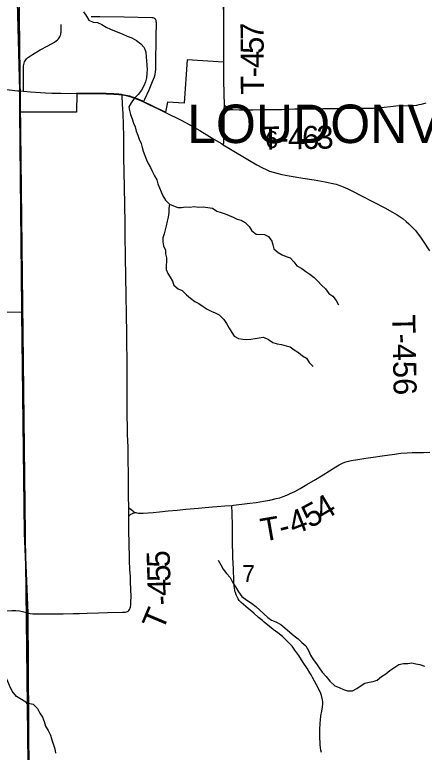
# Model space of a CAD drawing. Extents: x -7.5 to 53.5, y 0 to 22.
# Drawn here: x 4.57 to 5.577, y 15.27 to 17.086 of the extents above; entities that cross this region are included whole.
import ezdxf

# ---------------------------------------------------------------- set-up
doc = ezdxf.new("R2010")
doc.units = 0
for name, color, linetype in [('GM_X_City_Street', 7, 'Continuous'), ('GM_X_Corporation', 7, 'Continuous'), ('GM_X_Corporation_Text', 7, 'Continuous'), ('GM_X_Minor_River', 7, 'Continuous'), ('GM_X_Section_Text', 7, 'Continuous'), ('GM_X_State_Route', 7, 'Continuous'), ('GM_X_Township_Road', 7, 'Continuous'), ('GM_X_Township_Road_Text', 7, 'Continuous'), ('SH_Data', 7, 'Continuous')]:
    doc.layers.add(name, color=color, linetype=linetype)

msp = doc.modelspace()

# ---------------------------------------------------------------- linework, layer by layer
at = {"layer": 'GM_X_City_Street'}
for points in [[(4.7575, 17.0819), (4.7794, 17.0816), (4.8388, 17.0806), (4.9069, 17.0795), (4.9095, 17.0792), (4.9118, 17.0787), (4.9131, 17.0781), (4.9141, 17.0774), (4.9151, 17.0763), (4.9159, 17.0754)], [(4.887, 16.8716), (4.89, 16.8786), (4.9002, 16.9015), (4.9087, 16.9217), (4.9133, 16.9333), (4.9151, 16.9392), (4.9163, 16.9452), (4.917, 16.9514), (4.9173, 16.9638), (4.9179, 17.0327), (4.9183, 17.0665), (4.9181, 17.0689), (4.918, 17.07), (4.9177, 17.0712), (4.9174, 17.0723), (4.9171, 17.0733), (4.9165, 17.0745), (4.9159, 17.0754)], [(4.5916, 16.8979), (4.5916, 16.9055), (4.5916, 16.9147), (4.5915, 16.93), (4.5912, 16.9515), (4.5916, 16.9607), (4.5919, 16.9636), (4.5927, 16.9673), (4.5937, 16.9702), (4.5951, 16.9729), (4.5968, 16.9755), (4.5988, 16.9778), (4.601, 16.9799), (4.6059, 16.9837), (4.6138, 16.9886), (4.6325, 16.9994), (4.6513, 17.0099), (4.6674, 17.019), (4.6725, 17.0225), (4.6749, 17.0244), (4.6771, 17.0266), (4.679, 17.029), (4.6806, 17.0316), (4.6819, 17.0344), (4.6829, 17.0373), (4.6836, 17.0404), (4.6839, 17.0434), (4.6841, 17.0496), (4.6839, 17.0619)]]:
    msp.add_lwpolyline(points, dxfattribs=at)
at = {"layer": 'GM_X_Corporation'}
for points in [[(4.6087, 14.5302), (4.6021, 15.6139), (4.594, 15.8096), (4.5873, 16.3533), (4.5872, 16.3635), (4.5826, 16.8462), (4.5822, 16.8992), (4.577, 17.1178), (4.5749, 17.2575), (4.5771, 17.6201), (4.5718, 18.1276), (4.5696, 18.2604), (4.5565, 19.1354), (5.0411, 19.1401), (6.0424, 19.1527), (6.0433, 19.1527), (6.5522, 19.1561), (7.544, 19.1455), (8.414, 19.1709), (8.5159, 19.1718), (8.9, 19.1887), (8.9, 20.9), (2.1, 20.9), (2.1, 14.1)], [(8.9, 14.1), (8.9, 19.1887), (8.5159, 19.1718), (8.414, 19.1709), (7.544, 19.1455), (6.5522, 19.1561), (6.0433, 19.1527), (6.0424, 19.1527), (5.0411, 19.1401), (4.5565, 19.1354), (4.5696, 18.2604), (4.5718, 18.1276), (4.5771, 17.6201), (4.5749, 17.2575), (4.577, 17.1178), (4.5822, 16.8992), (4.5826, 16.8462), (4.5872, 16.3635), (4.5873, 16.3533), (4.594, 15.8096), (4.6021, 15.6139), (4.6087, 14.5302)], [(5.0833, 17.1238), (5.0837, 16.9694), (4.9938, 16.9748), (4.9864, 16.8684), (4.9457, 16.8713), (4.9407, 16.8459), (4.9209, 16.8557), (4.9011, 16.8652), (4.8868, 16.8721), (4.8846, 16.8733), (4.8731, 16.878), (4.8617, 16.8824), (4.8529, 16.8854), (4.8439, 16.8876), (4.8348, 16.8893), (4.8335, 16.8895), (4.8256, 16.8905), (4.8133, 16.8915), (4.7947, 16.8921), (4.7224, 16.8928), (4.722, 16.8462), (4.5826, 16.8462), (4.5873, 16.3533), (3.9378, 16.3588)]]:
    msp.add_lwpolyline(points, dxfattribs=at)
at = {"layer": 'GM_X_Minor_River'}
for points in [[(4.7393, 17.0935), (4.746, 17.0825), (4.7524, 17.0729), (4.763, 17.0679), (4.7732, 17.0667), (4.7838, 17.062), (4.7947, 17.0559), (4.8056, 17.0504), (4.8155, 17.0469), (4.8257, 17.0423), (4.8355, 17.038), (4.8464, 17.0338), (4.8581, 17.0291), (4.8698, 17.0229), (4.8804, 17.0149), (4.8879, 17.0053), (4.8927, 16.9943), (4.893, 16.9822), (4.8944, 16.9723), (4.8947, 16.9617), (4.8954, 16.9514), (4.8949, 16.9412), (4.8941, 16.931), (4.8917, 16.9211), (4.8871, 16.9113), (4.8817, 16.9003), (4.8733, 16.8894), (4.8637, 16.8797), (4.8564, 16.8695), (4.8507, 16.8597), (4.8525, 16.8502), (4.8547, 16.8403), (4.8588, 16.8296), (4.8617, 16.8194), (4.8658, 16.8099), (4.8688, 16.7996), (4.8725, 16.7897), (4.8762, 16.7802), (4.8806, 16.7691), (4.8832, 16.7596), (4.8862, 16.7501), (4.8902, 16.7399), (4.8943, 16.7292), (4.8984, 16.7197), (4.9036, 16.7102), (4.9085, 16.6991), (4.9133, 16.6892), (4.9193, 16.6797), (4.9219, 16.6698), (4.926, 16.6599), (4.9304, 16.65), (4.9341, 16.6401), (4.9405, 16.6298), (4.9503, 16.6199), (4.9601, 16.616), (4.9707, 16.6113), (4.9802, 16.6116), (4.9896, 16.6131), (5.0006, 16.6122), (5.0109, 16.6144), (5.0218, 16.612), (5.0336, 16.6134), (5.045, 16.6118), (5.0567, 16.6098), (5.0673, 16.6029), (5.0775, 16.5994), (5.0873, 16.5963), (5.0971, 16.5916), (5.1069, 16.5877), (5.1171, 16.5831), (5.127, 16.58), (5.1368, 16.5746), (5.1465, 16.5646)], [(4.9503, 16.6199), (4.9487, 16.6093), (4.9493, 16.599), (4.9477, 16.5877), (4.9446, 16.5778), (4.9423, 16.5665), (4.9375, 16.5468), (4.9344, 16.5366), (4.934, 16.5267), (4.9362, 16.5172), (4.9406, 16.5069), (4.9405, 16.4975), (4.9431, 16.488), (4.943, 16.4785), (4.9422, 16.4686), (4.9425, 16.4591), (4.9466, 16.4493), (4.9522, 16.4397), (4.9582, 16.4302), (4.9615, 16.4203), (4.9717, 16.4111), (4.9819, 16.4072), (4.9928, 16.3969), (5.0026, 16.3885), (5.0127, 16.3804), (5.0225, 16.3754), (5.0331, 16.3681), (5.0429, 16.3615), (5.0531, 16.3561), (5.0629, 16.3526), (5.0731, 16.3472), (5.084, 16.3358), (5.0907, 16.3258), (5.0971, 16.3144), (5.1038, 16.3041), (5.1098, 16.2946), (5.12, 16.2892), (5.131, 16.2872), (5.1408, 16.2867), (5.1511, 16.2874), (5.1617, 16.2892), (5.1712, 16.291), (5.1818, 16.2924), (5.1939, 16.2862), (5.2048, 16.2789), (5.2154, 16.2758), (5.2264, 16.2742), (5.2373, 16.271), (5.2472, 16.2683), (5.2574, 16.261), (5.2679, 16.2545), (5.2781, 16.2464), (5.2879, 16.2403), (5.2942, 16.2303), (5.3033, 16.2208), (5.304, 16.2204)], [(5.1465, 16.5646), (5.1533, 16.5543), (5.1642, 16.5455), (5.1843, 16.5453), (5.1941, 16.5399), (5.202, 16.5289), (5.2049, 16.5194), (5.2075, 16.5095), (5.2176, 16.501), (5.2278, 16.4949), (5.238, 16.491), (5.2479, 16.4879), (5.2565, 16.4779), (5.2636, 16.468), (5.2761, 16.4611), (5.2859, 16.4538), (5.2957, 16.4472), (5.3062, 16.4388), (5.316, 16.4296), (5.325, 16.42), (5.3348, 16.4109), (5.343, 16.3998), (5.3528, 16.3929), (5.3607, 16.3826), (5.3667, 16.3723), (5.3663, 16.3719)], [(5.07, 15.7435), (5.0773, 15.7318), (5.0827, 15.7213), (5.0912, 15.7103), (5.0996, 15.7005), (5.1058, 15.6888), (5.1127, 15.6775), (5.12, 15.665), (5.1288, 15.6541), (5.1406, 15.6447), (5.1525, 15.6372), (5.1628, 15.629), (5.1731, 15.62), (5.1922, 15.6019), (5.2017, 15.5955), (5.212, 15.5915), (5.2242, 15.5847), (5.2341, 15.5768), (5.2471, 15.5663), (5.2574, 15.5573), (5.2669, 15.5494), (5.2765, 15.5408), (5.2864, 15.5321), (5.2926, 15.5208), (5.2976, 15.5091), (5.3038, 15.4989), (5.3126, 15.4883), (5.3187, 15.4782), (5.326, 15.4672), (5.3363, 15.4571), (5.3448, 15.4457), (5.3578, 15.4341), (5.368, 15.43), (5.3787, 15.4244), (5.3882, 15.4211), (5.4007, 15.4219), (5.4113, 15.427), (5.4218, 15.435), (5.4316, 15.4404), (5.4418, 15.4431), (5.4517, 15.4447), (5.4619, 15.4475), (5.4724, 15.4567), (5.4825, 15.4636), (5.4931, 15.4713), (5.5051, 15.4797), (5.5153, 15.4862), (5.5266, 15.489), (5.5373, 15.4887), (5.5471, 15.4903), (5.557, 15.4881), (5.5665, 15.4863), (5.5782, 15.4822)], [(4.5998, 15.3899), (4.5998, 15.3918), (4.5861, 15.4), (4.5742, 15.4075), (4.5631, 15.4203), (4.5573, 15.4343), (4.5511, 15.4486), (4.5457, 15.4603), (4.5388, 15.4717), (4.5303, 15.483), (4.5185, 15.4927), (4.5063, 15.5006), (4.4956, 15.5054), (4.485, 15.5095), (4.4728, 15.5151), (4.4651, 15.5256), (4.4593, 15.5377), (4.455, 15.5509), (4.4511, 15.563)], [(4.5998, 15.3918), (4.6155, 15.3884), (4.6255, 15.3779), (4.6316, 15.3669), (4.6378, 15.3567), (4.6421, 15.3458), (4.6456, 15.3348), (4.6517, 15.3235), (4.6575, 15.3125), (4.6607, 15.3008), (4.6642, 15.2906), (4.6681, 15.2785), (4.6697, 15.2682)]]:
    msp.add_lwpolyline(points, dxfattribs=at)
at = {"layer": 'GM_X_State_Route'}
msp.add_line((4.5824, 16.8987), (4.5916, 16.8979), dxfattribs=at)
for points in [[(4.5083, 16.9057), (4.5157, 16.9051), (4.5373, 16.9029), (4.556, 16.9011), (4.5777, 16.8991), (4.5824, 16.8987)], [(4.5916, 16.8979), (4.6083, 16.8965), (4.6456, 16.8939), (4.6612, 16.8933), (4.6832, 16.8927), (4.7226, 16.8923), (4.7949, 16.8916), (4.8135, 16.8909), (4.8258, 16.8899), (4.8337, 16.8889)], [(4.8337, 16.8889), (4.835, 16.8888), (4.8441, 16.8871), (4.8531, 16.8848), (4.8619, 16.8818), (4.8734, 16.8774), (4.8849, 16.8728), (4.887, 16.8716)], [(4.887, 16.8716), (4.9013, 16.8647), (4.9211, 16.8552), (4.9409, 16.8453)], [(4.9409, 16.8453), (4.979, 16.8267), (5.0009, 16.8149), (5.025, 16.8009), (5.0596, 16.7801), (5.0783, 16.7688), (5.0829, 16.766)], [(5.0829, 16.766), (5.0967, 16.7578), (5.1474, 16.7274), (5.1656, 16.7166), (5.1797, 16.709), (5.1882, 16.705), (5.1964, 16.7014), (5.2054, 16.6982), (5.2145, 16.6959), (5.2268, 16.693), (5.2451, 16.6899), (5.2788, 16.6841), (5.3062, 16.6797), (5.3337, 16.675), (5.3488, 16.6718), (5.3608, 16.6687), (5.3696, 16.6659), (5.3782, 16.6625), (5.3895, 16.6575), (5.4023, 16.6512), (5.4228, 16.6406), (5.4806, 16.6105), (5.4997, 16.6001), (5.5104, 16.5938), (5.5181, 16.5887), (5.5256, 16.5833), (5.5328, 16.5774), (5.5397, 16.5712), (5.5463, 16.5647), (5.5548, 16.5557), (5.5606, 16.5486), (5.5698, 16.5361), (5.575, 16.5284), (5.59, 16.5048)]]:
    msp.add_lwpolyline(points, dxfattribs=at)
at = {"layer": 'GM_X_Township_Road'}
for points in [[(5.0839, 16.9689), (5.0839, 16.9888), (5.084, 16.9961), (5.084, 17.0058), (5.0841, 17.0141), (5.0842, 17.0233), (5.0843, 17.0368), (5.0844, 17.0475), (5.0844, 17.0541), (5.0844, 17.0598), (5.0843, 17.066), (5.0841, 17.0767), (5.084, 17.0858), (5.0839, 17.0941), (5.0838, 17.1028), (5.0837, 17.1094), (5.0836, 17.113), (5.0835, 17.1188), (5.0835, 17.1232), (5.0834, 17.1243)], [(5.0856, 16.8635), (5.0856, 16.8644), (5.0856, 16.8734), (5.0855, 16.8827), (5.0851, 16.9004), (5.0847, 16.9164), (5.0842, 16.9347), (5.0841, 16.9407), (5.0841, 16.9502), (5.0839, 16.9689)], [(4.846, 16.2638), (4.8459, 16.2721), (4.8454, 16.3032), (4.8446, 16.3466), (4.8444, 16.3653), (4.8441, 16.3786), (4.8439, 16.3923), (4.8436, 16.409), (4.8433, 16.4274), (4.8428, 16.4584), (4.8425, 16.4739), (4.8422, 16.5048), (4.8419, 16.5295), (4.8417, 16.5512), (4.8413, 16.5792), (4.8408, 16.6113), (4.8404, 16.6289), (4.8401, 16.6506), (4.8395, 16.6755), (4.8393, 16.6848), (4.8388, 16.7096), (4.8385, 16.7251), (4.8386, 16.75), (4.8383, 16.7686), (4.838, 16.7873), (4.8372, 16.8152), (4.8362, 16.8431), (4.8352, 16.8649), (4.8339, 16.8864), (4.8337, 16.8889)], [(5.2713, 16.8543), (5.2912, 16.8546), (5.3232, 16.8548), (5.3293, 16.855), (5.3352, 16.8552), (5.3409, 16.8555), (5.3538, 16.8556), (5.3745, 16.8557), (5.389, 16.856), (5.4124, 16.8563), (5.4242, 16.8565), (5.4381, 16.8564), (5.4526, 16.8562), (5.4628, 16.857), (5.4722, 16.8579), (5.4785, 16.8585), (5.494, 16.8603), (5.5076, 16.8617), (5.5233, 16.8625), (5.5395, 16.862), (5.5462, 16.8624), (5.552, 16.8626), (5.5588, 16.8639), (5.5648, 16.865), (5.5705, 16.8662), (5.5824, 16.8695)], [(5.0854, 16.848), (5.0855, 16.8537), (5.0856, 16.8635)], [(5.0854, 16.848), (5.0898, 16.85), (5.0933, 16.8512), (5.0956, 16.8519), (5.0969, 16.8522), (5.0983, 16.8524), (5.0993, 16.8525)], [(5.0856, 16.8635), (5.0915, 16.8587), (5.095, 16.856), (5.0993, 16.8525)], [(5.0993, 16.8525), (5.1, 16.8526), (5.1062, 16.8527), (5.1217, 16.8523), (5.1372, 16.8522), (5.1558, 16.8522), (5.1788, 16.8525), (5.1932, 16.8527), (5.2272, 16.8532), (5.2583, 16.8541), (5.2713, 16.8543)], [(5.0829, 16.766), (5.0833, 16.768), (5.084, 16.7707), (5.0844, 16.7739), (5.0847, 16.7787), (5.0847, 16.7818), (5.0847, 16.788), (5.0848, 16.8035), (5.0848, 16.8082), (5.0848, 16.8136), (5.0848, 16.8183), (5.085, 16.8259), (5.0853, 16.8377), (5.0854, 16.8436), (5.0854, 16.848)], [(4.8495, 15.9561), (4.8491, 15.9903), (4.8486, 16.0214), (4.8476, 16.0524), (4.8472, 16.0742), (4.8467, 16.0959), (4.8468, 16.1021), (4.8467, 16.1188), (4.8467, 16.1318), (4.8467, 16.144), (4.8467, 16.1571), (4.8466, 16.1704), (4.8465, 16.1848), (4.8464, 16.2039), (4.8462, 16.2287), (4.8461, 16.2504), (4.846, 16.2638)], [(5.104, 15.8782), (5.1084, 15.8786), (5.1485, 15.8832), (5.1639, 15.8854), (5.1823, 15.8885), (5.1975, 15.8913), (5.2127, 15.8947), (5.2217, 15.8971), (5.2306, 15.8998), (5.2393, 15.9031), (5.2478, 15.907), (5.2588, 15.9126), (5.2725, 15.92), (5.2886, 15.9293), (5.3101, 15.9419), (5.3287, 15.9531), (5.3601, 15.9731), (5.3681, 15.9778), (5.3765, 15.9819), (5.3822, 15.9843), (5.3881, 15.9863), (5.3941, 15.9878), (5.4025, 15.9895), (5.4093, 15.9906), (5.4337, 15.9944), (5.4521, 15.997), (5.4736, 16), (5.5043, 16.0045), (5.5197, 16.0063), (5.5351, 16.0075), (5.5475, 16.0081), (5.5755, 16.0086), (5.5909, 16.0095)], [(4.8505, 15.8724), (4.8503, 15.8788), (4.85, 15.8947), (4.8498, 15.9128), (4.8497, 15.9283), (4.8497, 15.9407), (4.8495, 15.9531), (4.8495, 15.9561)], [(4.8505, 15.8724), (4.8559, 15.8677), (4.8592, 15.8651), (4.8618, 15.8633), (4.8645, 15.8618), (4.8676, 15.8604)], [(4.8505, 15.8518), (4.8505, 15.8593), (4.8505, 15.8695), (4.8505, 15.8724)], [(4.8676, 15.8604), (4.8705, 15.8597), (4.8742, 15.8592), (4.8796, 15.8589), (4.8858, 15.859), (4.9106, 15.8609), (4.926, 15.8625), (4.9476, 15.8646), (4.9692, 15.8665), (4.9909, 15.8686), (5.0223, 15.8715), (5.0381, 15.8728), (5.0563, 15.8743), (5.0682, 15.8752), (5.0868, 15.8766), (5.104, 15.8782)], [(5.3245, 15.2693), (5.3232, 15.2756), (5.3223, 15.2819), (5.3214, 15.2882), (5.321, 15.2952), (5.3205, 15.3038), (5.3203, 15.3063), (5.3202, 15.3182), (5.3206, 15.3306), (5.321, 15.3368), (5.3215, 15.3429), (5.322, 15.3491), (5.3232, 15.3596), (5.3256, 15.3717), (5.3272, 15.3818), (5.3277, 15.3892), (5.3276, 15.3921), (5.3276, 15.3946), (5.3271, 15.3996), (5.3244, 15.4097), (5.3226, 15.4149), (5.3187, 15.4237), (5.3124, 15.4363), (5.3027, 15.4544), (5.299, 15.4607), (5.2962, 15.4656), (5.2904, 15.4753), (5.2798, 15.4916), (5.2689, 15.5081), (5.259, 15.5217), (5.2522, 15.5311), (5.2445, 15.5397), (5.2378, 15.5463), (5.2285, 15.5556), (5.2175, 15.5646), (5.2057, 15.5727), (5.1963, 15.5801), (5.1839, 15.5908), (5.1791, 15.5944), (5.1697, 15.6023), (5.158, 15.6127), (5.1442, 15.6245), (5.127, 15.6392), (5.1224, 15.6443), (5.1198, 15.6482), (5.1148, 15.6577), (5.1127, 15.664), (5.1116, 15.667), (5.111, 15.6697), (5.1102, 15.6739), (5.1098, 15.6791), (5.1093, 15.6883), (5.1091, 15.6915), (5.1086, 15.7019), (5.1081, 15.7118), (5.1077, 15.7221), (5.1068, 15.7501), (5.106, 15.7936), (5.1054, 15.834), (5.105, 15.8526), (5.1045, 15.865), (5.1043, 15.8713), (5.104, 15.8782)], [(4.8505, 15.8518), (4.8531, 15.8542), (4.8556, 15.8562), (4.8581, 15.8576), (4.8604, 15.8586), (4.8636, 15.8596), (4.8676, 15.8604)], [(4.8511, 15.7955), (4.8509, 15.8044), (4.8507, 15.8172), (4.8506, 15.8248), (4.8505, 15.8347), (4.8504, 15.8426), (4.8505, 15.8518)], [(4.6023, 15.6133), (4.6041, 15.6128), (4.6079, 15.612), (4.6147, 15.6113), (4.622, 15.6109), (4.634, 15.6108), (4.6613, 15.611), (4.6892, 15.6114), (4.7139, 15.6116), (4.7294, 15.6119), (4.7481, 15.6124), (4.776, 15.6133), (4.7978, 15.614), (4.835, 15.615), (4.8413, 15.6155), (4.8445, 15.6161), (4.8475, 15.6172), (4.8488, 15.6179), (4.8503, 15.6192), (4.8522, 15.6219), (4.8536, 15.6249), (4.8545, 15.6279), (4.8554, 15.6342), (4.8558, 15.6404), (4.8559, 15.6528), (4.855, 15.69), (4.8543, 15.7055), (4.854, 15.7087), (4.8533, 15.723), (4.8524, 15.7403), (4.8522, 15.7503), (4.8519, 15.7602), (4.8516, 15.7727), (4.8513, 15.7831), (4.8512, 15.7916), (4.8511, 15.7955)], [(4.344, 15.6154), (4.3515, 15.6155), (4.3639, 15.6157), (4.3794, 15.6158), (4.398, 15.616), (4.4167, 15.6162), (4.4354, 15.6164), (4.4603, 15.6166), (4.4821, 15.6168), (4.5069, 15.6175), (4.5225, 15.6178), (4.5442, 15.6185), (4.5629, 15.6191), (4.5722, 15.6189), (4.5815, 15.6181), (4.5887, 15.6171), (4.5954, 15.6155), (4.6023, 15.6133)]]:
    msp.add_lwpolyline(points, dxfattribs=at)
at = {"layer": 'SH_Data'}
msp.add_lwpolyline([(8.9, 19.1896), (4.5566, 19.1336), (4.6149, 14.11), (4.6151, 14.1)], dxfattribs=at)

# ---------------------------------------------------------------- texts
at = {"layer": 'GM_X_Corporation_Text'}
msp.add_text('LOUDONVILLE', height=0.094697, rotation=0, dxfattribs=at).set_placement((4.9943, 16.7702))
at = {"layer": 'GM_X_Section_Text'}
for s, p in [('6', (5.1867, 16.7579)), ('7', (5.1297, 15.6893))]:
    msp.add_text(s, height=0.0419, rotation=0, dxfattribs=at).set_placement(p)
at = {"layer": 'GM_X_Township_Road_Text'}
for s, height, rotation, p in [('7', 0.0568, 90.3861, (5.1823, 17.0248)), ('5', 0.0568, 90.3218, (5.1825, 16.99)), ('4', 0.0568, 90.3049, (5.1827, 16.9553)), ('-', 0.0568, 90.2987, (5.1828, 16.9321)), ('T', 0.0568, 90.2973, (5.183, 16.8897)), ('T', 0.0568, 0.8829, (5.1765, 16.7537)), ('4', 0.0568, 0.9182, (5.2423, 16.7547)), ('6', 0.0568, 1.0227, (5.2775, 16.7553)), ('3', 0.0568, 1.4372, (5.3129, 16.7559)), ('-', 0.0568, 0.8821, (5.219, 16.7544)), ('T-456', 0.05682, 271.1137, (5.4984, 16.3473)), ('4', 0.0568, 30.7421, (5.3291, 15.8387)), ('5', 0.0568, 28.3152, (5.296, 15.8208)), ('4', 0.0568, 21.0862, (5.2563, 15.805)), ('T', 0.0568, 9.8717, (5.1801, 15.7887)), ('-', 0.0568, 14.3375, (5.2267, 15.797)), ('5', 0.0568, 91.6186, (4.952, 15.7259)), ('5', 0.0568, 91.7186, (4.9531, 15.6909)), ('4', 0.0568, 91.5302, (4.954, 15.6557)), ('-', 0.0568, 92.4197, (4.955, 15.6326)), ('T', 0.0568, 67.1537, (4.9337, 15.5668))]:
    msp.add_text(s, height=height, rotation=rotation, dxfattribs=at).set_placement(p)

doc.saveas('drawing.dxf')
